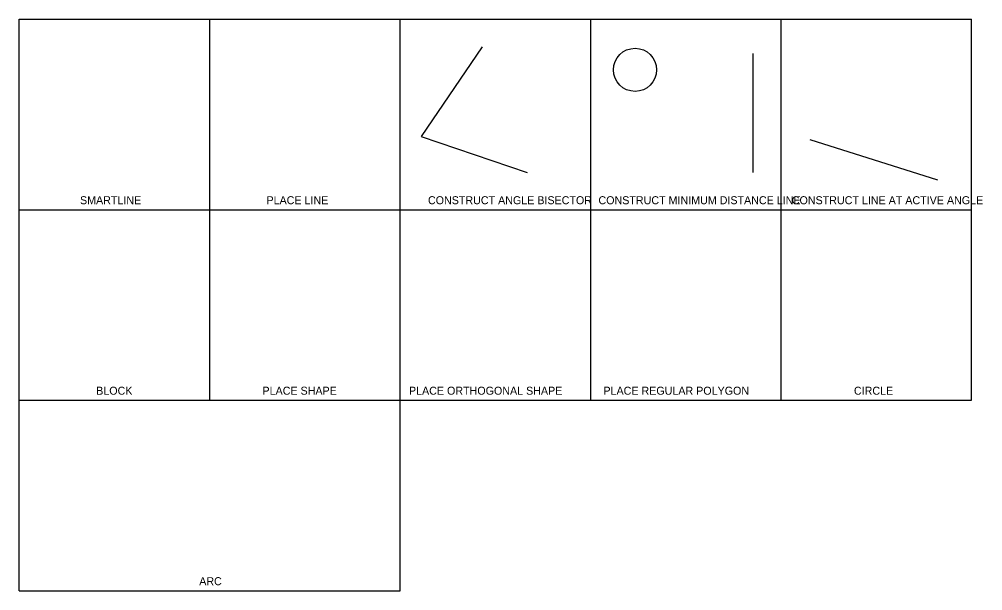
# Model space of a CAD drawing. Extents: x 257 to 762, y -76 to 224.
import ezdxf

# ---------------------------------------------------------------- set-up
doc = ezdxf.new("R2010")
doc.units = 0
doc.layers.add('Common-Notes', color=7, linetype='Continuous')
doc.layers.add('Scratch-1', color=7, linetype='Continuous')

msp = doc.modelspace()

# ---------------------------------------------------------------- linework, layer by layer
at = {"layer": 'Scratch-1'}
for p, q in [((256.6, 123.55), (256.6, 223.55)), ((256.6, 223.55), (756.6, 223.55)), ((356.6, 23.55), (356.6, 223.55)), ((456.6, -76.45), (456.6, 223.55)), ((556.6, 23.55), (556.6, 223.55)), ((656.6, 23.55), (656.6, 223.55)), ((756.6, 23.55), (756.6, 223.55)), ((641.67, 205.58), (641.67, 143.11)), ((738.8, 139), (671.87, 160.28)), ((256.6, -76.45), (256.6, 123.55)), ((256.6, 123.55), (756.6, 123.55)), ((256.6, 123.55), (556.6, 123.55)), ((256.6, 23.55), (756.6, 23.55)), ((256.6, -76.45), (456.6, -76.45))]:
    msp.add_line(p, q, dxfattribs=at)
msp.add_lwpolyline([(499.57, 209.02), (467.65, 161.99), (523.25, 143.11)], dxfattribs=at)
msp.add_circle((579.88, 197), 11.33, dxfattribs=at)

# ---------------------------------------------------------------- texts
at = {"layer": 'Common-Notes'}
for s, p in [('SMARTLINE', (288.49, 126.45)), ('PLACE LINE', (386.39, 126.45)), ('CONSTRUCT ANGLE BISECTOR', (471.16, 126.45)), ('CONSTRUCT MINIMUM DISTANCE LINE', (560.67, 126.45)), ('CONSTRUCT LINE AT ACTIVE ANGLE', (662.17, 126.45)), ('BLOCK', (296.98, 26.45)), ('PLACE SHAPE', (384.29, 26.45)), ('PLACE ORTHOGONAL SHAPE', (461.19, 26.45)), ('PLACE REGULAR POLYGON', (563.28, 26.45)), ('CIRCLE', (694.79, 26.45)), ('ARC', (351.08, -73.55))]:
    msp.add_text(s, height=4.2, dxfattribs=at).set_placement(p)

doc.saveas('drawing.dxf')
